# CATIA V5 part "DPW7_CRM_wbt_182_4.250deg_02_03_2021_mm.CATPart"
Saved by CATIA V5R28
Part number: DPW7_CRM_wbt_182_4.250deg_02_03_2021
Bounding box of the stored display mesh (mm): x 2349.5 to 66711.891, y 0 to 29465.711, z 2310.119 to 8715.756
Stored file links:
  Z:\Scratch\04_CAD_Allgemein\Flight2Jig\Output\DPW-7\CATPart\DPW7_CRM_wbt_182_4.250deg_02_03_2021.CATPart
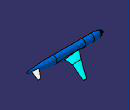
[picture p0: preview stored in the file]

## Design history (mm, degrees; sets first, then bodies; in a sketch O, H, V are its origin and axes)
Set1
  DatumSurface1 "Clean_Wing"
  DatumSurface2 "Fuselage"
  DatumSurface3 "HTP"
  DatumSurface4 "Symmetry"
  DatumSurface5 "Farfield"
Body1 (main body)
